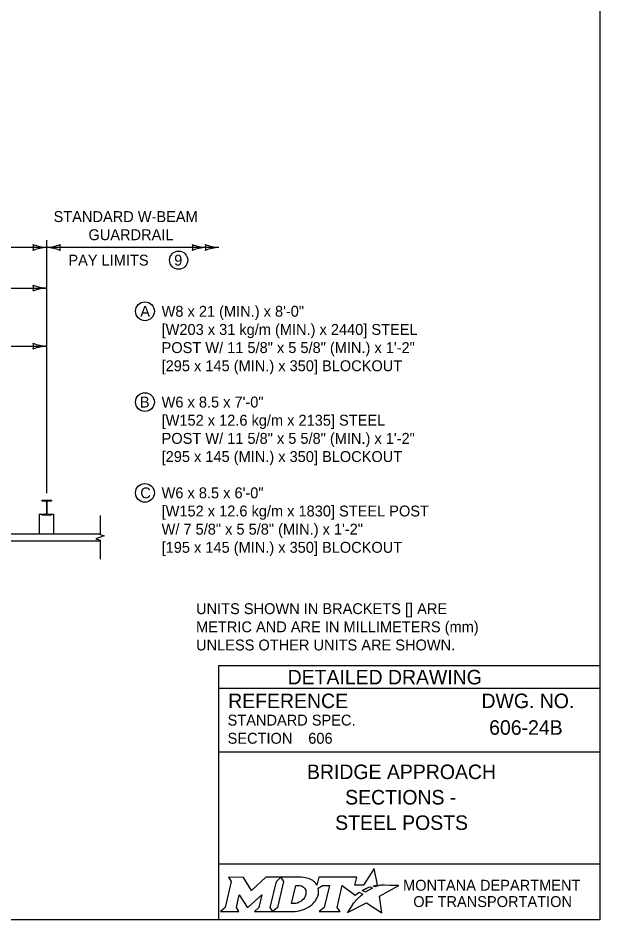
# Model space of a CAD drawing. Extents: x 49991.4 to 50021, y 49987.6 to 50011.4.
# Drawn here: x 50013.547 to 50016.75, y 49987.799 to 49992.766 of the extents above; entities that cross this region are included whole.
import ezdxf

# ---------------------------------------------------------------- set-up
doc = ezdxf.new("R2010")
doc.units = 0
for name, color, linetype in [('Default', 7, 'Continuous'), ('Level 1', 7, 'Continuous'), ('Level 2', 7, 'Continuous'), ('Level 3', 7, 'Continuous'), ('Level 5', 7, 'Continuous'), ('Level 6', 7, 'Continuous')]:
    doc.layers.add(name, color=color, linetype=linetype)

msp = doc.modelspace()

# ---------------------------------------------------------------- linework, layer by layer
at = {"layer": 'Default'}
for points in [[(50015.5126, 49987.9811), (50015.5023, 49987.9867), (50015.5139, 49987.9895), (50015.5255, 49987.9915), (50015.5081, 49988.0816), (50015.4486, 49987.9903), (50015.4013, 49987.9896), (50015.4116, 49988.0337), (50015.2024, 49988.0338), (50015.1923, 49987.9913), (50015.1865, 49987.9996)], [(50014.7056, 49988.0338), (50014.7197, 49988.0104), (50014.6862, 49987.8671), (50014.6605, 49987.8446), (50014.7621, 49987.8446), (50014.7486, 49987.8674), (50014.7648, 49987.9375), (50014.8085, 49987.8685), (50014.8138, 49987.8685), (50014.8889, 49987.938), (50014.8725, 49987.8669), (50014.8478, 49987.8449), (50014.9494, 49987.8449), (50014.9356, 49987.8682), (50014.9688, 49988.0106)], [(50014.9688, 49988.0106), (50014.9941, 49988.0338), (50014.9117, 49988.0338), (50014.8321, 49987.9608), (50014.7876, 49988.0335), (50014.7056, 49988.0338)], [(50015.1077, 49988.0338), (50014.9941, 49988.0338), (50015.0088, 49988.0109), (50014.9749, 49987.8671), (50014.9494, 49987.8449), (50015.06, 49987.8449)], [(50015.1317, 49987.9471), (50015.1305, 49987.939), (50015.1273, 49987.9297), (50015.1231, 49987.9215), (50015.1175, 49987.914), (50015.111, 49987.9071), (50015.1031, 49987.9008), (50015.0948, 49987.8961), (50015.0857, 49987.8922), (50015.0766, 49987.8899), (50015.0674, 49987.889), (50015.0515, 49987.889), (50015.0751, 49987.989), (50015.0911, 49987.989), (50015.0987, 49987.9884), (50015.1063, 49987.9865), (50015.1129, 49987.9835), (50015.119, 49987.9793), (50015.1238, 49987.9743), (50015.1275, 49987.9683), (50015.1302, 49987.9621), (50015.1318, 49987.9547), (50015.1318, 49987.9517), (50015.1317, 49987.9471)], [(50015.1991, 49987.9747), (50015.2237, 49987.9878), (50015.2606, 49987.9878), (50015.232, 49987.8673), (50015.2045, 49987.8446), (50015.3207, 49987.8446), (50015.3037, 49987.8675), (50015.3319, 49987.9877), (50015.4032, 49987.936), (50015.4243, 49987.9511), (50015.444, 49987.9402)], [(50015.3882, 49987.8843), (50015.3729, 49987.8599), (50015.3682, 49987.8524), (50015.3624, 49987.8438), (50015.3601, 49987.8395), (50015.4654, 49987.8926), (50015.5493, 49987.8375), (50015.5362, 49987.9302), (50015.6431, 49987.9886), (50015.5938, 49987.9894), (50015.5637, 49987.9898), (50015.5429, 49987.9901), (50015.5361, 49987.9886), (50015.5312, 49987.9874), (50015.5228, 49987.9851), (50015.5126, 49987.9811)], [(50015.4622, 49987.9535), (50015.4598, 49987.9518), (50015.4415, 49987.9614), (50015.4518, 49987.9671), (50015.4559, 49987.9693), (50015.4645, 49987.9733), (50015.4702, 49987.9759), (50015.4781, 49987.9789), (50015.4854, 49987.9816), (50015.4972, 49987.9742), (50015.4932, 49987.9721), (50015.4886, 49987.9696), (50015.4844, 49987.9674), (50015.4794, 49987.9645), (50015.4775, 49987.9634), (50015.4748, 49987.9618), (50015.4723, 49987.9604), (50015.47, 49987.9588), (50015.4674, 49987.957), (50015.4647, 49987.9552), (50015.4622, 49987.9535)], [(50015.4021, 49987.9004), (50015.4021, 49987.9004)], [(50015.1057, 49987.8522), (50015.1141, 49987.8548), (50015.1271, 49987.8602), (50015.1475, 49987.8712)]]:
    msp.add_lwpolyline(points, dxfattribs=at)
for centre, radius, start, end in [((50015.1308, 49987.9554), 0.0709, 339.5329, 15.8582), ((50015.0868, 49987.9727), 0.1183, 300.9103, 339.1383)]:
    msp.add_arc(centre, radius, start, end, dxfattribs=at)
for centre, major_axis, ratio, start_param, end_param in [((50015.1056, 49987.9864), (0.0834, -0.0037), 0.568097, 0.61298, 1.570796), ((50015.1612, 49987.9937), (0.0361, -0.0295), 0.469099, 1.225588, 1.570796), ((50015.3952, 49987.8923), (-0.00694, -0.00806), 0.008222, 0, 3.137361), ((50015.4119, 49987.9106), (-0.0098, -0.0102), 0.016458, 3.141593, 6.279097), ((50015.4329, 49987.9305), (-0.0112, -0.0097), 0.021651, 3.157348, 6.283185), ((50015.0603, 49987.9932), (0, 0.1484), 0.987302, 3.139398, 3.456847)]:
    msp.add_ellipse(centre, major_axis=major_axis, ratio=ratio, start_param=start_param, end_param=end_param, dxfattribs=at)
at = {"layer": 'Level 1'}
for p, q in [((50013.6778, 49990.1099), (50013.7303, 49990.1099)), ((50013.6778, 49990.1099), (50013.6778, 49990.1071)), ((50013.6778, 49990.1071), (50013.6958, 49990.1071)), ((50013.7029, 49990.0999), (50013.7029, 49990.0399)), ((50013.7052, 49990.0999), (50013.7052, 49990.0399)), ((50013.7123, 49990.1071), (50013.7303, 49990.1071)), ((50013.7303, 49990.1099), (50013.7303, 49990.1071)), ((50013.664, 49990.0328), (50013.664, 49989.9261)), ((50013.664, 49990.0328), (50013.6771, 49990.0328)), ((50013.6771, 49990.0299), (50013.6771, 49990.0328)), ((50013.6771, 49990.0299), (50013.731, 49990.0299)), ((50013.6778, 49990.0299), (50013.6778, 49990.0328)), ((50013.6778, 49990.0328), (50013.6958, 49990.0328)), ((50013.7123, 49990.0328), (50013.7303, 49990.0328)), ((50013.7303, 49990.0299), (50013.7303, 49990.0328)), ((50013.731, 49990.0299), (50013.731, 49990.0328)), ((50013.731, 49990.0328), (50013.7441, 49990.0328)), ((50013.7441, 49989.9261), (50013.7441, 49990.0328)), ((50008.8185, 49989.9261), (50013.9981, 49989.9261)), ((50008.8185, 49989.886), (50013.9981, 49989.886))]:
    msp.add_line(p, q, dxfattribs=at)
msp.add_lwpolyline([(49999.3835, 49998.9992), (50016.7501, 49998.9992), (50016.7501, 49987.7988), (49999.3835, 49987.7988)], close=True, dxfattribs=at)
for centre, start, end in [((50013.6958, 49990.0999), 0, 90), ((50013.7123, 49990.0999), 90, 180), ((50013.6958, 49990.0399), 270, 0), ((50013.7123, 49990.0399), 180, 270)]:
    msp.add_arc(centre, 0.00714, start, end, dxfattribs=at)
at = {"layer": 'Level 2'}
for centre, radius in [((50014.4308, 49991.4326), 0.05), ((50014.2454, 49991.151), 0.0517), ((50014.2454, 49990.651), 0.0517), ((50014.2454, 49990.151), 0.0517)]:
    msp.add_circle(centre, radius, dxfattribs=at)
at = {"layer": 'Level 3'}
for p, q in [((50013.7041, 49991.5426), (50013.7041, 49990.1499)), ((50014.6522, 49991.5026), (50009.702, 49991.5026)), ((50011.2028, 49991.2792), (50013.7041, 49991.2792)), ((50009.702, 49990.9592), (50013.7041, 49990.9592))]:
    msp.add_line(p, q, dxfattribs=at)
for centre, radius, start, end in [((50013.713, 49991.7192), 0.2167, 247.456, 267.6395), ((50013.5791, 49991.5026), 0.0534, 342.1388, 17.8612), ((50013.7153, 49991.2758), 0.2271, 92.8273, 112.0772), ((50013.6929, 49991.7295), 0.2271, 272.8273, 292.0772), ((50013.6951, 49991.2861), 0.2167, 67.456, 87.6395), ((50013.829, 49991.5026), 0.0534, 162.1388, 197.8612), ((50014.5895, 49991.7192), 0.2167, 247.456, 267.6395), ((50014.4556, 49991.5026), 0.0534, 342.1388, 17.8612), ((50014.5918, 49991.2758), 0.2271, 92.8273, 112.0772), ((50014.6611, 49991.7192), 0.2167, 247.456, 267.6395), ((50014.5272, 49991.5026), 0.0534, 342.1388, 17.8612), ((50014.6634, 49991.2758), 0.2271, 92.8273, 112.0772), ((50013.713, 49991.4957), 0.2167, 247.456, 267.6395), ((50013.5791, 49991.2792), 0.0534, 342.1388, 17.8612), ((50013.7153, 49991.0523), 0.2271, 92.8273, 112.0772), ((50013.713, 49991.1757), 0.2167, 247.456, 267.6395), ((50013.5791, 49990.9592), 0.0534, 342.1388, 17.8612), ((50013.7153, 49990.7323), 0.2271, 92.8273, 112.0772)]:
    msp.add_arc(centre, radius, start, end, dxfattribs=at)
at = {"layer": 'Level 5'}
for p, q in [((50016.7501, 49989.1988), (50014.6501, 49989.1988)), ((50014.6501, 49989.1988), (50014.6501, 49987.7988)), ((50016.7501, 49989.0738), (50014.6501, 49989.0738)), ((50016.3862, 49988.8587), (50016.3862, 49988.8587)), ((50015.1444, 49988.7993), (50015.1444, 49988.7993)), ((50016.7501, 49988.7238), (50014.6501, 49988.7238)), ((50015.7001, 49988.4747), (50015.7001, 49988.4747)), ((50016.7501, 49988.1057), (50014.6501, 49988.1057))]:
    msp.add_line(p, q, dxfattribs=at)
at = {"layer": 'Level 6'}
for p, q in [((50013.9981, 49990.0261), (50013.9981, 49989.9218)), ((50014.0203, 49989.9139), (50013.9758, 49989.8981)), ((50013.9758, 49989.8981), (50013.9981, 49989.8902)), ((50013.9981, 49989.9218), (50014.0203, 49989.9139)), ((50013.9981, 49989.8902), (50013.9981, 49989.786))]:
    msp.add_line(p, q, dxfattribs=at)

# ---------------------------------------------------------------- texts
at = {"layer": 'Default'}
for s, p in [('MONTANA DEPARTMENT', (50015.6663, 49987.96)), ('OF TRANSPORTATION', (50015.7225, 49987.87))]:
    msp.add_text(s, height=0.06, dxfattribs=at).set_placement(p)
at = {"layer": 'Level 2'}
for s, height, p in [('STANDARD W-BEAM', 0.06, (50013.7425, 49991.6426)), ('GUARDRAIL', 0.06, (50013.9344, 49991.5426)), ('PAY LIMITS', 0.06, (50013.824, 49991.4026)), ('9', 0.06, (50014.4063, 49991.4027)), ('A', 0.06, (50014.2197, 49991.121)), ('W8 x 21 (MIN.) x 8\'-0" ', 0.06, (50014.3371, 49991.121)), ('[W203 x 31 kg/m (MIN.) x 2440] STEEL ', 0.06, (50014.3371, 49991.021)), ('POST W/ 11 5/8" x 5 5/8" (MIN.) x 1\'-2" ', 0.06, (50014.3371, 49990.921)), ('[295 x 145 (MIN.) x 350] BLOCKOUT', 0.06, (50014.3371, 49990.821)), ('B', 0.06, (50014.2177, 49990.621)), ('W6 x 8.5 x 7\'-0" ', 0.06, (50014.3371, 49990.621)), ('[W152 x 12.6 kg/m x 2135] STEEL', 0.06, (50014.3371, 49990.521)), ('POST W/ 11 5/8" x 5 5/8" (MIN.) x 1\'-2" ', 0.06, (50014.3371, 49990.421)), ('[295 x 145 (MIN.) x 350] BLOCKOUT', 0.06, (50014.3371, 49990.321)), ('C', 0.06, (50014.2199, 49990.121)), ('W6 x 8.5 x 6\'-0" ', 0.06, (50014.3371, 49990.121)), ('[W152 x 12.6 kg/m x 1830] STEEL POST ', 0.06, (50014.3371, 49990.021)), ('W/ 7 5/8" x 5 5/8" (MIN.) x 1\'-2" ', 0.06, (50014.3371, 49989.921)), ('[195 x 145 (MIN.) x 350] BLOCKOUT', 0.06, (50014.3371, 49989.821)), ('UNITS SHOWN IN BRACKETS [] ARE ', 0.06, (50014.5268, 49989.4832)), ('METRIC AND ARE IN MILLIMETERS (mm) ', 0.06, (50014.5268, 49989.3832)), ('UNLESS OTHER UNITS ARE SHOWN.', 0.06, (50014.5268, 49989.2832)), ('606-24B', 0.08, (50016.1402, 49988.8187)), ('606', 0.06, (50015.1444, 49988.7693)), ('BRIDGE APPROACH', 0.08, (50015.1375, 49988.5747)), ('SECTIONS -', 0.08, (50015.3474, 49988.4347)), ('STEEL POSTS', 0.08, (50015.2924, 49988.2947))]:
    msp.add_text(s, height=height, dxfattribs=at).set_placement(p)
at = {"layer": 'Level 5'}
for s, height, p in [('DETAILED DRAWING', 0.0799, (50015.0311, 49989.0963)), ('REFERENCE', 0.08, (50014.7037, 49988.9654)), ('DWG. NO.', 0.08, (50016.0979, 49988.9654)), ('STANDARD SPEC.', 0.06, (50014.7004, 49988.8694)), ('SECTION', 0.06, (50014.7004, 49988.7694))]:
    msp.add_text(s, height=height, dxfattribs=at).set_placement(p)

doc.saveas('drawing.dxf')
